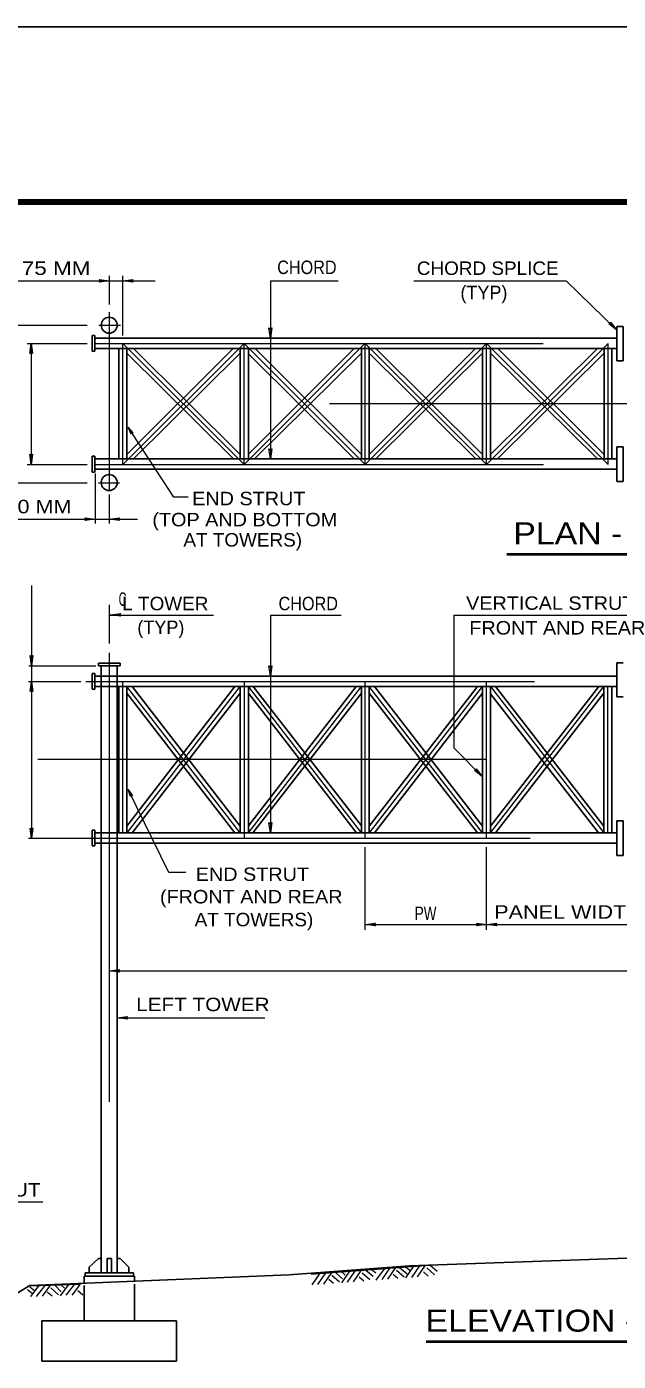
# Model space of a CAD drawing. Extents: x 312601.858 to 312602.699, y 144420.109 to 144420.704.
# Drawn here: x 312602.0439 to 312602.1757, y 144420.4062 to 144420.7035 of the extents above; entities that cross this region are included whole.
import ezdxf
from ezdxf.enums import TextEntityAlignment as Align

# ---------------------------------------------------------------- set-up
doc = ezdxf.new("R2010")
doc.units = 0
doc.header["$LTSCALE"] = 0.0012
doc.linetypes.add('DOT_DASHED', pattern=[7.7, 5, -1.2, 0.3, -1.2])
doc.linetypes.add('LONG_DASHED', pattern=[7.5, 6, -1.5])
for name, color, linetype, lineweight in [('1', 7, 'Continuous', 25), ('2', 7, 'Continuous', 13), ('39', 7, 'Continuous', 13)]:
    doc.layers.add(name, color=color, linetype=linetype, lineweight=lineweight)

msp = doc.modelspace()

# ---------------------------------------------------------------- hatches: boundary and pattern name
at = {"layer": '39'}
for points in [[(312602.0673, 144420.613), (312602.0672, 144420.6127), (312602.0665, 144420.6143), (312602.0676, 144420.613)], [(312602.0672, 144420.5322), (312602.067, 144420.532), (312602.0665, 144420.5336), (312602.0675, 144420.5322)]]:
    msp.add_hatch(color=256, dxfattribs=at).paths.add_polyline_path(points)

# ---------------------------------------------------------------- linework, layer by layer
at = {"layer": '1', "lineweight": 13}
for p, q in [((312601.9318, 144420.6469), (312602.0623, 144420.6469)), ((312602.0623, 144420.648), (312602.0623, 144420.6416)), ((312602.0623, 144420.6469), (312602.0653, 144420.6469)), ((312602.0653, 144420.6347), (312602.0653, 144420.648)), ((312602.0653, 144420.6469), (312602.0725, 144420.6469)), ((312602.0982, 144420.6469), (312602.1133, 144420.6469)), ((312602.1302, 144420.6469), (312602.1641, 144420.6469)), ((312602.1641, 144420.6469), (312602.1754, 144420.6359)), ((312602.0335, 144420.637), (312602.0574, 144420.637)), ((312602.044, 144420.6329), (312602.0574, 144420.6329)), ((312602.0449, 144420.6329), (312602.0449, 144420.606)), ((312602.044, 144420.606), (312602.0574, 144420.606)), ((312602.0335, 144420.6019), (312602.0574, 144420.6019)), ((312602.0592, 144420.5928), (312602.0592, 144420.604)), ((312602.0623, 144420.5993), (312602.0623, 144420.5928)), ((312602.0623, 144420.5938), (312602.0686, 144420.5938)), ((312602.0623, 144420.5747), (312602.0623, 144420.5661)), ((312602.0622, 144420.5724), (312602.0855, 144420.5724)), ((312602.0982, 144420.5724), (312602.114, 144420.5724)), ((312602.1392, 144420.5428), (312602.1392, 144420.5724)), ((312602.1392, 144420.5724), (312602.1835, 144420.5724)), ((312602.0444, 144420.5611), (312602.0593, 144420.5611)), ((312602.0443, 144420.5576), (312602.056, 144420.5576)), ((312602.045, 144420.5576), (312602.045, 144420.5227)), ((312602.1392, 144420.5428), (312602.1455, 144420.5364)), ((312602.0443, 144420.5227), (312602.0562, 144420.5227)), ((312602.1193, 144420.5023), (312602.1193, 144420.5207)), ((312602.1464, 144420.5023), (312602.1464, 144420.5207)), ((312602.0605, 144420.5127), (312602.0605, 144420.5139)), ((312602.0623, 144420.4932), (312602.4035, 144420.4932)), ((312602.0641, 144420.4827), (312602.097, 144420.4827)), ((312601.9969, 144420.4417), (312602.0475, 144420.4417)), ((312602.0605, 144420.431), (312602.0605, 144420.4322))]:
    msp.add_line(p, q, dxfattribs=at)
at = {"layer": '1', "linetype": 'DOT_DASHED', "lineweight": 13}
for p, q in [((312602.06, 144420.637), (312602.0648, 144420.637)), ((312602.0623, 144420.6399), (312602.0623, 144420.6002)), ((312602.059, 144420.6329), (312602.4095, 144420.6329)), ((312602.0924, 144420.6329), (312602.0653, 144420.606)), ((312602.0653, 144420.606), (312602.0653, 144420.6327)), ((312602.0924, 144420.6329), (312602.1193, 144420.606)), ((312602.0924, 144420.606), (312602.0924, 144420.6329)), ((312602.1193, 144420.6329), (312602.1464, 144420.606)), ((312602.1464, 144420.6329), (312602.1193, 144420.606)), ((312602.1193, 144420.606), (312602.1193, 144420.6329)), ((312602.1735, 144420.6329), (312602.1464, 144420.606)), ((312602.1464, 144420.6329), (312602.1735, 144420.606)), ((312602.1464, 144420.606), (312602.1464, 144420.6329)), ((312602.1735, 144420.606), (312602.1735, 144420.6329)), ((312602.4114, 144420.6195), (312602.0618, 144420.6195)), ((312602.0591, 144420.606), (312602.4097, 144420.606)), ((312602.0599, 144420.6019), (312602.0646, 144420.6019)), ((312602.0623, 144420.564), (312602.0623, 144420.4298)), ((312602.0571, 144420.5576), (312602.4098, 144420.5576)), ((312602.0653, 144420.5239), (312602.0653, 144420.5576)), ((312602.0924, 144420.5576), (312602.0924, 144420.5227)), ((312602.1193, 144420.5227), (312602.1193, 144420.5576)), ((312602.1464, 144420.5227), (312602.1464, 144420.5576)), ((312602.0915, 144420.5239), (312602.0662, 144420.5565)), ((312602.0663, 144420.5239), (312602.0915, 144420.5565)), ((312602.1185, 144420.5239), (312602.0933, 144420.5565)), ((312602.0933, 144420.5239), (312602.1185, 144420.5565)), ((312602.1455, 144420.5239), (312602.1202, 144420.5565)), ((312602.1203, 144420.5239), (312602.1455, 144420.5565)), ((312602.1473, 144420.5565), (312602.1725, 144420.5239)), ((312602.1473, 144420.5239), (312602.1725, 144420.5565)), ((312602.1734, 144420.5239), (312602.1734, 144420.5565)), ((312602.0464, 144420.5403), (312602.1686, 144420.5403)), ((312602.0561, 144420.5227), (312602.4099, 144420.5227))]:
    msp.add_line(p, q, dxfattribs=at)
at = {"layer": '1'}
for p, q in [((312602.0585, 144420.6347), (312602.0585, 144420.6312)), ((312602.0585, 144420.6347), (312602.0591, 144420.6347)), ((312602.0591, 144420.6347), (312602.0591, 144420.6312)), ((312602.0591, 144420.6341), (312602.1754, 144420.6341)), ((312602.1754, 144420.6367), (312602.1754, 144420.6291)), ((312602.0585, 144420.6312), (312602.0591, 144420.6312)), ((312602.0591, 144420.6318), (312602.1754, 144420.6318)), ((312602.0644, 144420.6072), (312602.0644, 144420.6318)), ((312602.0662, 144420.6072), (312602.0662, 144420.6318)), ((312602.0915, 144420.6082), (312602.0677, 144420.6318)), ((312602.0915, 144420.6072), (312602.0915, 144420.6318)), ((312602.0933, 144420.6083), (312602.1169, 144420.6318)), ((312602.0933, 144420.6072), (312602.0933, 144420.6318)), ((312602.1185, 144420.6072), (312602.1185, 144420.6318)), ((312602.1202, 144420.6072), (312602.1202, 144420.6318)), ((312602.1455, 144420.6082), (312602.1217, 144420.6318)), ((312602.1455, 144420.6072), (312602.1455, 144420.6318)), ((312602.1473, 144420.6072), (312602.1473, 144420.6318)), ((312602.1473, 144420.6082), (312602.1711, 144420.6318)), ((312602.1726, 144420.6072), (312602.1726, 144420.6318)), ((312602.1743, 144420.6072), (312602.1743, 144420.6318)), ((312602.09, 144420.6072), (312602.0662, 144420.6308)), ((312602.0947, 144420.6072), (312602.1185, 144420.6308)), ((312602.144, 144420.6072), (312602.1202, 144420.6308)), ((312602.1488, 144420.6072), (312602.1726, 144420.6308)), ((312602.1754, 144420.6291), (312602.1768, 144420.6291)), ((312602.0585, 144420.6078), (312602.0585, 144420.6043)), ((312602.0585, 144420.6078), (312602.0591, 144420.6078)), ((312602.0591, 144420.6078), (312602.0591, 144420.6043)), ((312602.1754, 144420.6099), (312602.1754, 144420.6022)), ((312602.0585, 144420.6043), (312602.0591, 144420.6043)), ((312602.0591, 144420.6072), (312602.1754, 144420.6072)), ((312602.0591, 144420.6049), (312602.1754, 144420.6049)), ((312602.1754, 144420.6022), (312602.1768, 144420.6022)), ((312602.0599, 144420.5617), (312602.0599, 144420.5611)), ((312602.0599, 144420.5617), (312602.0647, 144420.5617)), ((312602.0599, 144420.5611), (312602.0647, 144420.5611)), ((312602.0605, 144420.5611), (312602.0605, 144420.4259)), ((312602.0641, 144420.5611), (312602.0641, 144420.4259)), ((312602.0647, 144420.5617), (312602.0647, 144420.5611)), ((312602.1754, 144420.5542), (312602.1754, 144420.5618)), ((312602.1754, 144420.5618), (312602.1768, 144420.5618)), ((312602.0585, 144420.5559), (312602.0585, 144420.5594)), ((312602.0585, 144420.5594), (312602.0591, 144420.5594)), ((312602.0591, 144420.5559), (312602.0591, 144420.5594)), ((312602.0591, 144420.5588), (312602.0605, 144420.5588)), ((312602.0641, 144420.5588), (312602.1754, 144420.5588)), ((312602.0585, 144420.5559), (312602.0591, 144420.5559)), ((312602.0591, 144420.5565), (312602.0605, 144420.5565)), ((312602.0641, 144420.5565), (312602.1754, 144420.5565)), ((312602.0644, 144420.5239), (312602.0644, 144420.5565)), ((312602.0662, 144420.5239), (312602.0662, 144420.5565)), ((312602.0903, 144420.5239), (312602.0662, 144420.555)), ((312602.0915, 144420.5254), (312602.0674, 144420.5565)), ((312602.0915, 144420.5239), (312602.0915, 144420.5565)), ((312602.0933, 144420.5239), (312602.0933, 144420.5565)), ((312602.0933, 144420.5255), (312602.1173, 144420.5565)), ((312602.0943, 144420.5239), (312602.1185, 144420.555)), ((312602.1185, 144420.5239), (312602.1185, 144420.5565)), ((312602.1202, 144420.5239), (312602.1202, 144420.5565)), ((312602.1444, 144420.5239), (312602.1202, 144420.555)), ((312602.1455, 144420.5254), (312602.1214, 144420.5565)), ((312602.1455, 144420.5239), (312602.1455, 144420.5565)), ((312602.1473, 144420.5239), (312602.1473, 144420.5565)), ((312602.1473, 144420.5254), (312602.1714, 144420.5565)), ((312602.1484, 144420.5239), (312602.1725, 144420.555)), ((312602.1725, 144420.5239), (312602.1725, 144420.5565)), ((312602.1743, 144420.5239), (312602.1743, 144420.5565)), ((312602.1754, 144420.5542), (312602.1768, 144420.5542)), ((312602.0585, 144420.5245), (312602.0585, 144420.521)), ((312602.0585, 144420.5245), (312602.0591, 144420.5245)), ((312602.0591, 144420.5245), (312602.0591, 144420.521)), ((312602.1754, 144420.5266), (312602.1754, 144420.5189)), ((312602.0591, 144420.5239), (312602.0605, 144420.5239)), ((312602.0591, 144420.5216), (312602.0605, 144420.5216)), ((312602.0641, 144420.5239), (312602.1754, 144420.5239)), ((312602.0641, 144420.5216), (312602.1754, 144420.5216)), ((312602.0585, 144420.521), (312602.0591, 144420.521)), ((312602.1754, 144420.5189), (312602.1768, 144420.5189)), ((312602.0628, 144420.4291), (312602.0628, 144420.4259)), ((312602.0569, 144420.4259), (312602.0569, 144420.4252)), ((312602.0569, 144420.4259), (312602.0677, 144420.4259)), ((312602.0578, 144420.4272), (312602.0578, 144420.4259)), ((312602.0667, 144420.4272), (312602.0667, 144420.4259)), ((312602.0677, 144420.4259), (312602.0677, 144420.4252)), ((312602.0446, 144420.4231), (312602.0311, 144420.415)), ((312602.0567, 144420.4252), (312602.0679, 144420.4252)), ((312602.0567, 144420.4252), (312602.0567, 144420.4236)), ((312602.0679, 144420.4252), (312602.0679, 144420.4241))]:
    msp.add_line(p, q, dxfattribs=at)
at = {"layer": '1', "linetype": 'LONG_DASHED'}
for p, q in [((312602.0662, 144420.6082), (312602.0899, 144420.6318)), ((312602.1185, 144420.6082), (312602.0948, 144420.6318)), ((312602.1202, 144420.6082), (312602.1439, 144420.6318)), ((312602.1726, 144420.6082), (312602.1489, 144420.6318)), ((312602.0677, 144420.6072), (312602.0914, 144420.6307)), ((312602.1169, 144420.6072), (312602.0932, 144420.6308)), ((312602.1217, 144420.6072), (312602.1455, 144420.6308)), ((312602.1711, 144420.6072), (312602.1473, 144420.6308)), ((312602.0605, 144420.5588), (312602.0641, 144420.5588)), ((312602.0605, 144420.5565), (312602.0641, 144420.5565)), ((312602.0662, 144420.5254), (312602.0903, 144420.5565)), ((312602.0674, 144420.5239), (312602.0915, 144420.555)), ((312602.1174, 144420.5239), (312602.0933, 144420.555)), ((312602.1185, 144420.5255), (312602.0944, 144420.5565)), ((312602.1202, 144420.5254), (312602.1444, 144420.5565)), ((312602.1214, 144420.5239), (312602.1455, 144420.555)), ((312602.1713, 144420.5239), (312602.1473, 144420.5549)), ((312602.1725, 144420.5254), (312602.1484, 144420.5565)), ((312602.0605, 144420.5239), (312602.0641, 144420.5239)), ((312602.0605, 144420.5216), (312602.0641, 144420.5216)), ((312602.0567, 144420.4231), (312602.0567, 144420.4152)), ((312602.0679, 144420.4234), (312602.0679, 144420.4152)), ((312602.0473, 144420.4152), (312602.0773, 144420.4152)), ((312602.0473, 144420.4062), (312602.0773, 144420.4062))]:
    msp.add_line(p, q, dxfattribs=at)
at = {"layer": '1', "lineweight": 13}
for points in [[(312602.0601, 144420.6472), (312602.0623, 144420.6469), (312602.0601, 144420.6466), (312602.0603, 144420.6469)], [(312602.0676, 144420.6466), (312602.0653, 144420.6469), (312602.0676, 144420.6472), (312602.0673, 144420.6469)], [(312602.174, 144420.6377), (312602.1754, 144420.6359), (312602.1736, 144420.6373), (312602.1739, 144420.6373)], [(312602.0985, 144420.6364), (312602.0982, 144420.6341), (312602.0979, 144420.6364), (312602.0982, 144420.6361)], [(312602.0446, 144420.6307), (312602.0449, 144420.6329), (312602.0452, 144420.6307), (312602.0449, 144420.6309)], [(312602.0452, 144420.6083), (312602.0449, 144420.606), (312602.0446, 144420.6083), (312602.0449, 144420.608)], [(312602.0985, 144420.6095), (312602.0982, 144420.6072), (312602.0979, 144420.6095), (312602.0982, 144420.6092)], [(312602.0569, 144420.5941), (312602.0591, 144420.5938), (312602.0569, 144420.5935), (312602.0571, 144420.5938)], [(312602.0646, 144420.5935), (312602.0623, 144420.5938), (312602.0646, 144420.5941), (312602.0643, 144420.5938)], [(312602.0649, 144420.5722), (312602.0626, 144420.5725), (312602.0649, 144420.5728), (312602.0646, 144420.5725)], [(312602.0453, 144420.5634), (312602.045, 144420.5611), (312602.0447, 144420.5634), (312602.045, 144420.5631)], [(312602.0985, 144420.5611), (312602.0982, 144420.5588), (312602.0979, 144420.5611), (312602.0982, 144420.5608)], [(312602.0447, 144420.5554), (312602.045, 144420.5576), (312602.0453, 144420.5554), (312602.045, 144420.5556)], [(312602.1441, 144420.5382), (312602.1455, 144420.5364), (312602.1437, 144420.5378), (312602.1441, 144420.5378)], [(312602.0453, 144420.525), (312602.045, 144420.5227), (312602.0447, 144420.525), (312602.045, 144420.5247)], [(312602.0985, 144420.5262), (312602.0982, 144420.5239), (312602.0979, 144420.5262), (312602.0982, 144420.5259)], [(312602.1216, 144420.5032), (312602.1193, 144420.5035), (312602.1216, 144420.5038), (312602.1213, 144420.5035)], [(312602.1442, 144420.5038), (312602.1464, 144420.5035), (312602.1442, 144420.5032), (312602.1444, 144420.5035)], [(312602.1487, 144420.5032), (312602.1464, 144420.5035), (312602.1487, 144420.5038), (312602.1484, 144420.5035)], [(312602.0646, 144420.4929), (312602.0623, 144420.4932), (312602.0646, 144420.4935), (312602.0643, 144420.4932)], [(312602.0664, 144420.4824), (312602.0641, 144420.4827), (312602.0664, 144420.483), (312602.0661, 144420.4827)]]:
    msp.add_lwpolyline(points, close=True, dxfattribs=at)
for points in [[(312602.0982, 144420.6469), (312602.0982, 144420.6341), (312602.0982, 144420.6072)], [(312602.0799, 144420.5987), (312602.0767, 144420.5987), (312602.0665, 144420.6143)], [(312601.9711, 144420.5938), (312602.058, 144420.5938), (312602.0623, 144420.5938)], [(312602.045, 144420.579), (312602.045, 144420.5611), (312602.045, 144420.5576)], [(312602.0982, 144420.5724), (312602.0982, 144420.5588), (312602.0982, 144420.5239)], [(312602.0794, 144420.5151), (312602.0756, 144420.5151), (312602.0665, 144420.5336)], [(312602.1193, 144420.5035), (312602.1464, 144420.5035), (312602.331, 144420.5035)]]:
    msp.add_lwpolyline(points, dxfattribs=at)
at = {"layer": '1'}
for points in [[(312602.1754, 144420.6367), (312602.1768, 144420.6367), (312602.1768, 144420.6291)], [(312602.1754, 144420.6099), (312602.1768, 144420.6099), (312602.1768, 144420.6022)], [(312602.1754, 144420.5266), (312602.1768, 144420.5266), (312602.1768, 144420.5189)], [(312602.0446, 144420.4231), (312602.1024, 144420.4255), (312602.1292, 144420.4275), (312602.2324, 144420.4311), (312602.3359, 144420.4277), (312602.363, 144420.4257), (312602.4208, 144420.4234)], [(312602.0578, 144420.4272), (312602.0599, 144420.4291), (312602.0605, 144420.4291)], [(312602.0628, 144420.4291), (312602.0618, 144420.4291), (312602.0618, 144420.4259)], [(312602.0667, 144420.4272), (312602.0647, 144420.4291), (312602.0641, 144420.4291)]]:
    msp.add_lwpolyline(points, dxfattribs=at)
at = {"layer": '1', "linetype": 'DOT_DASHED', "lineweight": 13}
msp.add_lwpolyline([(312602.0653, 144420.6329), (312602.0924, 144420.606), (312602.1193, 144420.633)], dxfattribs=at)
at = {"layer": '1'}
for centre in [(312602.06229, 144420.63701), (312602.06229, 144420.60195)]:
    msp.add_circle(centre, 0.00178, dxfattribs=at)
at = {"layer": '2', "lineweight": 40}
for p, q in [((312602.1509, 144420.586), (312602.3141, 144420.586)), ((312602.1329, 144420.4106), (312602.3166, 144420.4106))]:
    msp.add_line(p, q, dxfattribs=at)
at = {"layer": '2'}
for p, q in [((312602.1073, 144420.4256), (312602.1347, 144420.4277)), ((312602.1088, 144420.4233), (312602.1106, 144420.4259)), ((312602.1101, 144420.4234), (312602.1119, 144420.426)), ((312602.1127, 144420.426), (312602.1143, 144420.4246)), ((312602.1141, 144420.4237), (312602.1159, 144420.4263)), ((312602.1141, 144420.4261), (312602.1149, 144420.4254)), ((312602.1154, 144420.4238), (312602.1172, 144420.4264)), ((312602.1167, 144420.4239), (312602.1185, 144420.4265)), ((312602.1187, 144420.4259), (312602.1204, 144420.4244)), ((312602.1195, 144420.4265), (312602.1211, 144420.4252)), ((312602.1209, 144420.4266), (312602.1217, 144420.4259)), ((312602.1218, 144420.4243), (312602.1237, 144420.4269)), ((312602.1231, 144420.4244), (312602.1249, 144420.427)), ((312602.1244, 144420.4245), (312602.1262, 144420.4271)), ((312602.1263, 144420.4265), (312602.128, 144420.425)), ((312602.127, 144420.4271), (312602.1287, 144420.4257)), ((312602.1284, 144420.4248), (312602.1302, 144420.4274)), ((312602.1284, 144420.4272), (312602.1293, 144420.4265)), ((312602.1297, 144420.4249), (312602.1315, 144420.4275)), ((312602.131, 144420.425), (312602.1328, 144420.4276)), ((312602.1323, 144420.4261), (312602.1334, 144420.4252)), ((312602.1331, 144420.427), (312602.1348, 144420.4255)), ((312602.1338, 144420.4276), (312602.1354, 144420.4263)), ((312602.0447, 144420.423), (312602.0558, 144420.4234)), ((312602.0448, 144420.4206), (312602.0467, 144420.4231)), ((312602.0461, 144420.4206), (312602.048, 144420.4231)), ((312602.0474, 144420.4207), (312602.0493, 144420.4232)), ((312602.0501, 144420.4232), (312602.0516, 144420.4217)), ((312602.0514, 144420.4208), (312602.0533, 144420.4233)), ((312602.0515, 144420.4232), (312602.0523, 144420.4225)), ((312602.0527, 144420.4209), (312602.0546, 144420.4234)), ((312602.054, 144420.4209), (312602.0559, 144420.4234)), ((312602.1075, 144420.4232), (312602.1093, 144420.4258)), ((312602.1112, 144420.4245), (312602.1123, 144420.4236)), ((312602.1119, 144420.4254), (312602.1136, 144420.4239)), ((312602.118, 144420.425), (312602.119, 144420.4241)), ((312602.1256, 144420.4256), (312602.1266, 144420.4247)), ((312602.0441, 144420.4222), (312602.0452, 144420.4213)), ((312602.0446, 144420.4228), (312602.0457, 144420.4219)), ((312602.0485, 144420.4217), (312602.0496, 144420.4208)), ((312602.0493, 144420.4226), (312602.051, 144420.421)), ((312602.0553, 144420.422), (312602.0564, 144420.421))]:
    msp.add_line(p, q, dxfattribs=at)
at = {"layer": '2', "linetype": 'LONG_DASHED', "lineweight": 25}
for p, q in [((312602.0473, 144420.4152), (312602.0473, 144420.4062)), ((312602.0773, 144420.4152), (312602.0773, 144420.4062))]:
    msp.add_line(p, q, dxfattribs=at)
at = {"layer": '39', "lineweight": 25}
msp.add_line((312601.8578, 144420.7035), (312602.6988, 144420.7035), dxfattribs=at)
at = {"layer": '39', "lineweight": 158}
msp.add_line((312601.9088, 144420.6645), (312602.6838, 144420.6645), dxfattribs=at)
at = {"layer": '39'}
for points in [[(312602.0673, 144420.613), (312602.0672, 144420.6127), (312602.0665, 144420.6143), (312602.0676, 144420.613)], [(312602.0672, 144420.5322), (312602.067, 144420.532), (312602.0665, 144420.5336), (312602.0675, 144420.5322)]]:
    msp.add_lwpolyline(points, close=True, dxfattribs=at)

# ---------------------------------------------------------------- texts
at = {"layer": '2'}
for s, height, width, p in [('0.5 (O.D. TOWER SHAFT + O.D. END STRUT) + 75 MM', 0.003, 1.25, (312601.9946, 144420.6482)), ('CHORD', 0.003, 0.9, (312602.10635, 144420.6484)), ('CHORD SPLICE', 0.003, 1.05, (312602.14665, 144420.6482)), ('END STRUT', 0.003, 1.1, (312602.0934, 144420.5969)), ('0.5 (O.D. TOWER SHAFT) + 150 MM', 0.003, 1.2, (312602.0137, 144420.5951)), ('(TOP AND BOTTOM', 0.003, 1.1, (312602.0925, 144420.5922)), ('PLAN - TYPICAL OVERHEAD SIGN SUPPORT', 0.0049, 1.15, (312602.23295, 144420.5882)), ('AT TOWERS)', 0.003, 1.05, (312602.09205, 144420.5877)), ('L TOWER', 0.003, 1.05, (312602.0748, 144420.5735)), ('CHORD', 0.003, 0.9, (312602.10665, 144420.5735)), ('VERTICAL STRUTS', 0.003, 1.1, (312602.16205, 144420.5736)), ('FRONT AND REAR', 0.003, 1.1, (312602.16215, 144420.5681)), ('END STRUT', 0.003, 1.1, (312602.0942, 144420.5132)), ('(FRONT AND REAR', 0.003, 1.1, (312602.09395, 144420.5082)), ('AT TOWERS)', 0.003, 1.05, (312602.09455, 144420.5031)), ('PW', 0.003, 0.75, (312602.1328, 144420.5045)), ('PANEL WIDTH = (TRUSS WIDTH - 300 MM) MIN, (TRUSS WIDTH + 150 MM) MAX', 0.003, 1.2, (312602.2385, 144420.5048)), ('ELEVATION - TYPICAL OVERHEAD SIGN SUPPORT', 0.0049, 1.15, (312602.2247, 144420.4128))]:
    msp.add_text(s, height=height, dxfattribs=dict(at, width=width)).set_placement(p, align=Align.CENTER)
for p in [(312602.1458, 144420.6428), (312602.0738, 144420.5682)]:
    msp.add_text('(TYP)', height=0.003, dxfattribs=at).set_placement(p, align=Align.CENTER)
for s, width, p in [('C', 0.6, (312602.0644, 144420.5745)), ('LEFT TOWER', 1.15, (312602.0683, 144420.4842)), ('BOTTOM STRUT', 1.15, (312602.0106, 144420.4429))]:
    msp.add_text(s, height=0.003, dxfattribs=dict(at, width=width)).set_placement(p)

doc.saveas('drawing.dxf')
